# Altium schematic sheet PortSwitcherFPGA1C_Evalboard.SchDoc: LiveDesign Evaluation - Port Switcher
size B; Organization: Altium Limited; Address1: L3, 12a Rodborough Rd; Address2: Frenchs Forest; Address3: NSW; Address4: Australia 2086
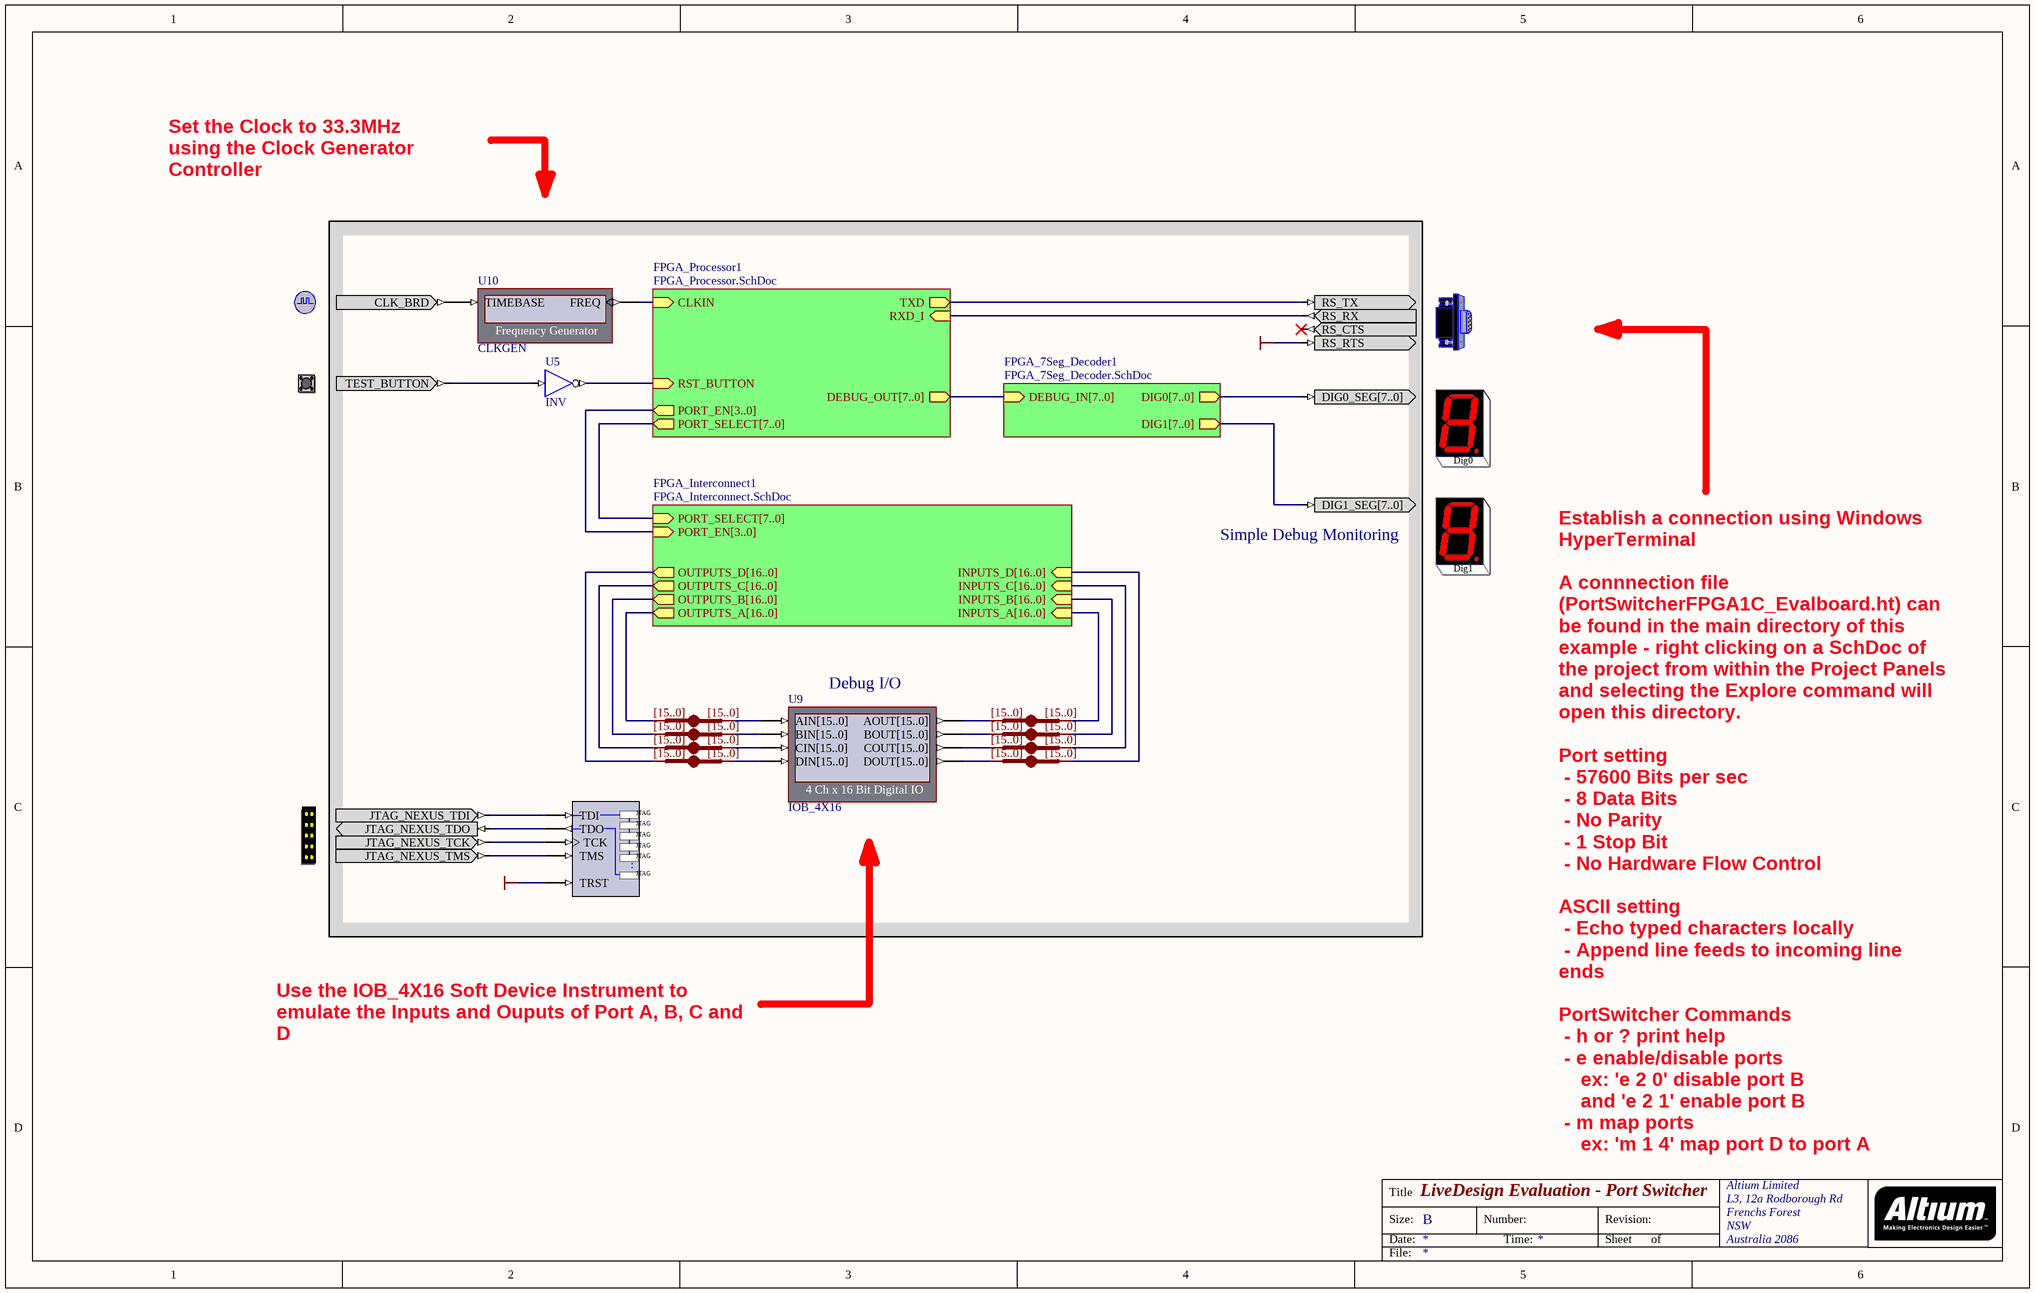
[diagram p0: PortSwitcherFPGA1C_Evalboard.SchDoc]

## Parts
7SEG0  7SEG0  (value not drawn)
7SEG1  7SEG1  (value not drawn)
CLOCK_BOARD  CLOCK_BOARD  (value not drawn)
JB_S2  IndexA: [15..0]  (hidden comment: JB)
JB_S3  IndexA: [15..0]  (hidden comment: JB)
JB_S4  IndexA: [15..0]  (hidden comment: JB)
JB_S5  IndexA: [15..0]  (hidden comment: JB)
JB_S6  IndexA: [15..0]  (hidden comment: JB)
JB_S7  IndexA: [15..0]  (hidden comment: JB)
JB_S8  IndexA: [15..0]  (hidden comment: JB)
JB_S9  IndexA: [15..0]  (hidden comment: JB)
NEXUS_JTAG_CONNECTOR  NEXUS_JTAG_CONNECTOR  (value not drawn)
NEXUS_JTAG_PORT  NEXUS_JTAG_PORT  (value not drawn)
RS232CNTR  RS232CNTR  (value not drawn)
TEST_BUTTON  TEST_BUTTON  (value not drawn)
U5  INV
U9  IOB_4X16
U10  CLKGEN

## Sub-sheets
FPGA_7Seg_Decoder1 = FPGA_7Seg_Decoder.SchDoc: DEBUG_IN[7..0] (in), DIG0[7..0] (out), DIG1[7..0] (out)
FPGA_Interconnect1 = FPGA_Interconnect.SchDoc: PORT_SELECT[7..0] (in), OUTPUTS_D[16..0] (out), OUTPUTS_C[16..0] (out), OUTPUTS_B[16..0] (out), OUTPUTS_A[16..0] (out), PORT_EN[3..0] (in), INPUTS_A[16..0] (in), INPUTS_B[16..0] (in), INPUTS_C[16..0] (in), INPUTS_D[16..0] (in)
FPGA_Processor1 = FPGA_Processor.SchDoc: TXD (out), RXD_I (in), CLKIN (in), RST_BUTTON (in), PORT_SELECT[7..0] (out), PORT_EN[3..0] (out), DEBUG_OUT[7..0] (out)

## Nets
VCC: NEXUS_JTAG_PORT.TRST RS232CNTR.RS_RTS
NetCLOCK_BOARD_CLK_BRD: CLOCK_BOARD.CLK_BRD U10.TIMEBASE
NetNEXUS_JTAG_CONNECTOR_JTAG_NEXUS_TCK: NEXUS_JTAG_CONNECTOR.JTAG_NEXUS_TCK NEXUS_JTAG_PORT.TCK
NetNEXUS_JTAG_CONNECTOR_JTAG_NEXUS_TDI: NEXUS_JTAG_CONNECTOR.JTAG_NEXUS_TDI NEXUS_JTAG_PORT.TDI
NetNEXUS_JTAG_CONNECTOR_JTAG_NEXUS_TDO: NEXUS_JTAG_CONNECTOR.JTAG_NEXUS_TDO NEXUS_JTAG_PORT.TDO
NetNEXUS_JTAG_CONNECTOR_JTAG_NEXUS_TMS: NEXUS_JTAG_CONNECTOR.JTAG_NEXUS_TMS NEXUS_JTAG_PORT.TMS
NetRS232CNTR_RS_RX: RS232CNTR.RS_RX ; sheet FPGA_Processor1/RXD_I
NetRS232CNTR_RS_TX: RS232CNTR.RS_TX ; sheet FPGA_Processor1/TXD
NetTEST_BUTTON_TEST_BUTTON: TEST_BUTTON.TEST_BUTTON U5.I
NetU5_O: U5.O ; sheet FPGA_Processor1/RST_BUTTON
NetU10_FREQ: U10.FREQ ; sheet FPGA_Processor1/CLKIN

Not connected (* = marked no-connect by the designer): 7SEG0 DIG0_SEG[7..0]; 7SEG1 DIG1_SEG[7..0]; JB_S2 A[0..0] B[0..0]; JB_S3 A[0..0] B[0..0]; JB_S4 A[0..0] B[0..0]; JB_S5 A[0..0] B[0..0]; JB_S6 A[0..0] B[0..0]; JB_S7 A[0..0] B[0..0]; JB_S8 A[0..0] B[0..0]; JB_S9 A[0..0] B[0..0]; RS232CNTR RS_CTS*; U9 AIN[15..0] AOUT[15..0] BIN[15..0] BOUT[15..0] CIN[15..0] COUT[15..0] DIN[15..0] DOUT[15..0]

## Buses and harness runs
bus sheet FPGA_7Seg_Decoder1/DEBUG_IN[7..0] = sheet FPGA_Processor1/DEBUG_OUT[7..0]
bus sheet FPGA_Interconnect1/PORT_EN[3..0] = sheet FPGA_Processor1/PORT_EN[3..0]
bus sheet FPGA_Interconnect1/PORT_SELECT[7..0] = sheet FPGA_Processor1/PORT_SELECT[7..0]

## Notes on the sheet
- Set the Clock to 33.3MHz using the Clock Generator Controller
- (near 7SEG1) Simple Debug Monitoring
- (near U9) Debug I/O
- Use the IOB_4X16 Soft Device Instrument to emulate the Inputs and Ouputs of Port A, B, C and D
- Establish a connection using Windows HyperTerminal
  A connnection file (PortSwitcherFPGA1C_Evalboard.ht) can be found in the main directory of this example - right clicking on a SchDoc of the project from within the Project Panels and selecting the Explore command will open this directory.
  Port setting
  - 57600 Bits per sec
  - 8 Data Bits
  - No Parity
  - 1 Stop Bit
  - No Hardware Flow Control
  ASCII setting
  - Echo typed characters locally
  - Append line feeds to incoming line ends
  PortSwitcher Commands
  - h or ? print help
  - e enable/disable ports
  ex: 'e 2 0' disable port B
  and 'e 2 1' enable port B
  - m map ports
  ex: 'm 1 4' map port D to port A
  and 'm 4 1' map port A to port D

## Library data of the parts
7SEG0 = 7SEG0: 7 Segment display module; PortComponent: True
7SEG1 = 7SEG1: 7 Segment display module; PortComponent: True
CLOCK_BOARD = CLOCK_BOARD: Global System Clock Supply; PortComponent: True
JB_S2-JB_S9 = JB: System BUS Joiner
NEXUS_JTAG_CONNECTOR = NEXUS_JTAG_CONNECTOR: JTAG Port; PortComponent: True
NEXUS_JTAG_PORT = NEXUS_JTAG_PORT: Soft Nexus-Chain Connector; NEXUS_JTAG_CONNECTOR: True
RS232CNTR = RS232CNTR: DCE Serial Port Connector; PortComponent: True
TEST_BUTTON = TEST_BUTTON: Test Button; PortComponent: True
U5 = INV: Inverter; ArchiveName: GENERIC; VHDLIB_SIM: GENERIC_LIB
U9 = IOB_4X16: 4 Ch x 16 Bit Digital IO; NEXUS_CORE: Instrument; NEXUS_JTAG_DEVICE: True; NEXUS_JTAG_ORDER: 0
U10 = CLKGEN: Frequency Generator; NEXUS_CORE: Instrument; NEXUS_JTAG_DEVICE: True; NEXUS_JTAG_ORDER: 0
